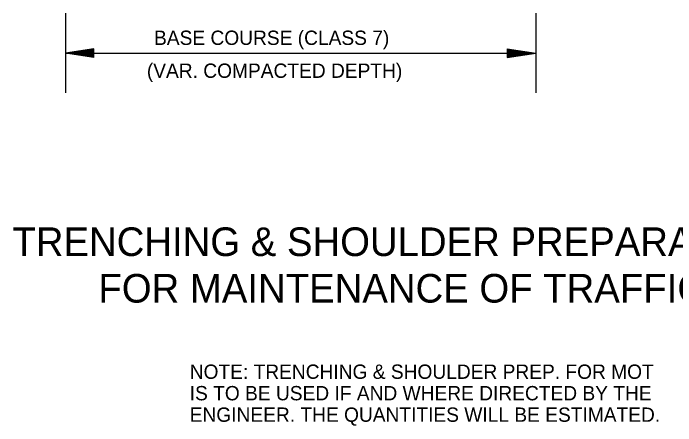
# Model space of a CAD drawing. Extents: x 1931522 to 1935523, y 600380 to 605075.
# Drawn here: x 1933239.3 to 1933516.8, y 604098.2 to 604271 of the extents above; entities that cross this region are included whole.
import ezdxf

# ---------------------------------------------------------------- set-up
doc = ezdxf.new("R2010")
doc.units = 0
doc.layers.add('Default', color=7, linetype='Continuous')
doc.layers.add('R_Border', color=7, linetype='Continuous')

msp = doc.modelspace()

# ---------------------------------------------------------------- linework, layer by layer
at = {"layer": 'Default'}
for p, q in [((1933261.14, 604271.02), (1933261.14, 604237.66)), ((1933458.15, 604271.02), (1933458.15, 604237.66)), ((1933273.14, 604256.14), (1933261.14, 604254.34)), ((1933261.14, 604254.34), (1933458.15, 604254.34)), ((1933273.14, 604252.54), (1933261.14, 604254.34)), ((1933273.14, 604255.84), (1933263.14, 604254.34)), ((1933273.14, 604252.84), (1933263.14, 604254.34)), ((1933273.14, 604255.53), (1933265.21, 604254.34)), ((1933273.14, 604253.15), (1933265.21, 604254.34)), ((1933273.14, 604255.23), (1933267.21, 604254.34)), ((1933273.14, 604253.45), (1933267.21, 604254.34)), ((1933273.14, 604254.93), (1933269.24, 604254.34)), ((1933273.14, 604253.76), (1933269.24, 604254.34)), ((1933273.14, 604254.62), (1933271.24, 604254.34)), ((1933273.14, 604254.06), (1933271.24, 604254.34)), ((1933273.14, 604252.54), (1933273.14, 604256.14)), ((1933446.15, 604256.14), (1933458.15, 604254.34)), ((1933446.15, 604256.14), (1933446.15, 604252.54)), ((1933446.15, 604255.84), (1933456.15, 604254.34)), ((1933446.15, 604255.53), (1933454.08, 604254.34)), ((1933446.15, 604255.23), (1933452.08, 604254.34)), ((1933446.15, 604254.92), (1933450.05, 604254.34)), ((1933446.15, 604254.62), (1933448.05, 604254.34)), ((1933446.15, 604252.54), (1933458.15, 604254.34)), ((1933446.15, 604253.75), (1933450.05, 604254.34)), ((1933446.15, 604253.15), (1933454.08, 604254.34)), ((1933446.15, 604252.84), (1933456.15, 604254.34)), ((1933446.15, 604253.45), (1933452.08, 604254.34)), ((1933446.15, 604254.06), (1933448.05, 604254.34))]:
    msp.add_line(p, q, dxfattribs=at)

# ---------------------------------------------------------------- texts
for s, height, p in [('BASE COURSE (CLASS 7)', 6, (1933298.29, 604257.75)), ('(VAR. COMPACTED DEPTH)', 6, (1933295.29, 604243.96)), ('TRENCHING & SHOULDER PREPARATION', 12, (1933238.96, 604169.32)), ('FOR MAINTENANCE OF TRAFFIC', 12, (1933274.99, 604149.82))]:
    msp.add_text(s, height=height, dxfattribs=at).set_placement(p)
at = {"layer": 'R_Border'}
for s, p in [('NOTE: TRENCHING & SHOULDER PREP. FOR MOT', (1933313.24, 604117.88)), ('IS TO BE USED IF AND WHERE DIRECTED BY THE', (1933313.24, 604108.88)), ('ENGINEER. THE QUANTITIES WILL BE ESTIMATED.', (1933313.24, 604099.88))]:
    msp.add_text(s, height=6, rotation=360, dxfattribs=at).set_placement(p)

doc.saveas('drawing.dxf')
